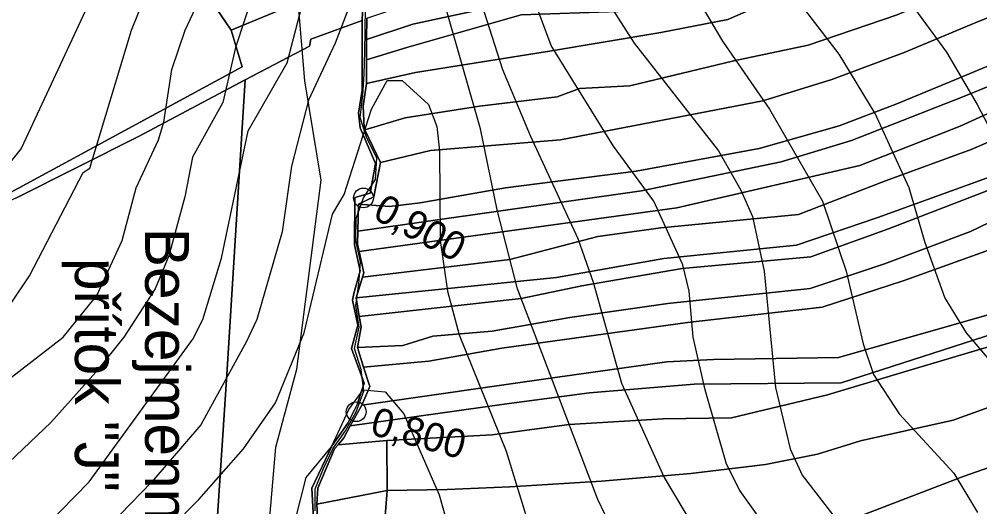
# Model space of a CAD drawing. Extents: x -510989 to -501240, y -1184665 to -1176098.
# Drawn here: x -509222.3 to -508784.4, y -1178657.4 to -1178435 of the extents above; entities that cross this region are included whole.
import ezdxf

# ---------------------------------------------------------------- set-up
doc = ezdxf.new("R2010")
doc.units = 0
for name, color, linetype in [('lesni_pozemek', 7, 'Continuous'), ('NAVRH_rozvodnice', 7, 'Continuous'), ('orna_puda', 7, 'Continuous'), ('ostatni_plocha_x_neplodna_puda', 7, 'Continuous'), ('STAV_systematicke_odvodneni', 7, 'Continuous'), ('trasovani_toku', 7, 'Continuous'), ('trvaly_travni_porost', 7, 'Continuous'), ('vodni_plocha_x_vodni_tok_v_koryt_prir_n_upr', 7, 'Continuous'), ('vrstevnice_01', 7, 'Continuous'), ('vrstevnice_02', 7, 'Continuous')]:
    doc.layers.add(name, color=color, linetype=linetype)

msp = doc.modelspace()

# ---------------------------------------------------------------- linework, layer by layer
at = {"layer": 'lesni_pozemek'}
for points in [[(-508725.81, -1178338.87), (-508747.38, -1178349.86), (-508771.63, -1178361.32), (-508829.64, -1178384.55), (-508872.53, -1178403.38), (-508910.67, -1178417.59), (-508947.16, -1178423.75), (-508989.77, -1178425.71), (-509042.9, -1178437.31), (-509063.9, -1178444.27), (-509063.87, -1178434.51), (-509050.17, -1178430.04), (-508985.42, -1178417.62), (-508954.71, -1178413.25), (-508914.71, -1178412.6), (-508860.28, -1178392.26), (-508835.76, -1178381.15), (-508767.15, -1178352.66), (-508746.52, -1178342.99), (-508726.34, -1178333.53)], [(-508724.96, -1178347.33), (-508750.56, -1178363.13), (-508780.12, -1178374.78), (-508825.23, -1178395.14), (-508865.91, -1178412.19), (-508905.35, -1178425.13), (-508949.3, -1178431.48), (-508993.44, -1178433.03), (-509045.63, -1178447.9), (-509063.93, -1178453.51), (-509063.9, -1178444.27), (-509042.9, -1178437.31), (-508989.77, -1178425.71), (-508947.16, -1178423.75), (-508910.67, -1178417.59), (-508872.53, -1178403.38), (-508829.64, -1178384.55), (-508771.63, -1178361.32), (-508747.38, -1178349.86), (-508725.81, -1178338.87)], [(-508724.96, -1178347.33), (-508723.35, -1178363.5), (-508739.8, -1178372.05), (-508775.1, -1178387.24), (-508823.72, -1178407.29), (-508879.66, -1178426.71), (-508899.31, -1178435.13), (-508929.85, -1178441.05), (-508980.55, -1178449.64), (-509041.66, -1178459.27), (-509063.96, -1178464.29), (-509063.93, -1178453.51), (-509045.63, -1178447.9), (-508993.44, -1178433.03), (-508949.3, -1178431.48), (-508905.35, -1178425.13), (-508865.91, -1178412.19), (-508825.23, -1178395.14), (-508780.12, -1178374.78), (-508750.56, -1178363.13)], [(-508717.91, -1178388.34), (-508711.8, -1178405.03), (-508747.07, -1178420.57), (-508786.54, -1178436.62), (-508818.83, -1178450.27), (-508851.86, -1178462.49), (-508883.28, -1178472.19), (-508975.6, -1178490), (-509034.85, -1178494.89), (-509057.51, -1178500.36), (-509064.65, -1178485.43), (-509046.4, -1178480), (-509012.39, -1178474.7), (-508976.98, -1178470.38), (-508966.94, -1178466.65), (-508943.87, -1178465.37), (-508896.48, -1178453.98), (-508862.6, -1178446.85), (-508822.14, -1178433.03), (-508752.43, -1178402.95)], [(-508710.55, -1178408.46), (-508709.09, -1178426.97), (-508754.59, -1178445.55), (-508797.64, -1178463.43), (-508822.28, -1178473.66), (-508848.44, -1178483.7), (-508884.95, -1178494.03), (-508941.04, -1178504.33), (-509000.63, -1178511.98), (-509039.44, -1178518.8), (-509053.47, -1178520.38), (-509067.62, -1178519.38), (-509060.62, -1178515.98), (-509057.51, -1178500.36), (-509034.85, -1178494.89), (-508975.6, -1178490), (-508883.28, -1178472.19), (-508851.86, -1178462.49), (-508818.83, -1178450.27), (-508786.54, -1178436.62), (-508747.07, -1178420.57), (-508711.8, -1178405.03)], [(-508708.36, -1178436.29), (-508792.21, -1178470.5), (-508842.92, -1178490.3), (-508874.96, -1178500.15), (-508938.58, -1178513.29), (-509067.91, -1178531.72), (-509067.62, -1178519.38), (-509053.47, -1178520.38), (-509039.44, -1178518.8), (-509000.63, -1178511.98), (-508941.04, -1178504.33), (-508884.95, -1178494.03), (-508848.44, -1178483.7), (-508822.28, -1178473.66), (-508797.64, -1178463.43), (-508754.59, -1178445.55), (-508709.09, -1178426.97)], [(-508707.48, -1178447.43), (-508757.4, -1178467.42), (-508793.43, -1178483.76), (-508839.17, -1178501.69), (-508922.58, -1178521.13), (-509067.34, -1178541), (-509068.05, -1178537.65), (-509067.91, -1178531.72), (-508938.58, -1178513.29), (-508874.96, -1178500.15), (-508842.92, -1178490.3), (-508792.21, -1178470.5), (-508708.36, -1178436.29)], [(-508706.46, -1178460.5), (-508722.75, -1178466.14), (-508765.33, -1178484.52), (-508788.4, -1178494.49), (-508827.36, -1178508.75), (-508867.12, -1178524.13), (-508929.73, -1178530.12), (-508958.54, -1178534.17), (-508998.7, -1178544.63), (-509065.84, -1178552.64), (-509065.25, -1178550.72), (-509067.34, -1178541), (-508922.58, -1178521.13), (-508839.17, -1178501.69), (-508793.43, -1178483.76), (-508757.4, -1178467.42), (-508707.48, -1178447.43)], [(-508722.75, -1178466.14), (-508706.46, -1178460.5), (-508705.39, -1178474.04), (-508749.78, -1178494.14), (-508781.31, -1178507.49), (-508830.87, -1178525.39), (-508867.91, -1178538.01), (-508928.36, -1178544.13), (-508977.41, -1178552.83), (-509068.71, -1178562.12), (-509065.84, -1178552.64), (-508998.7, -1178544.63), (-508958.54, -1178534.17), (-508929.73, -1178530.12), (-508867.12, -1178524.13), (-508827.36, -1178508.75), (-508788.4, -1178494.49), (-508765.33, -1178484.52)], [(-508704.77, -1178481.97), (-508738.88, -1178496.86), (-508783.53, -1178514.19), (-508825.98, -1178530.66), (-508861.42, -1178543.38), (-508920.04, -1178548.71), (-508965.85, -1178556.61), (-508993.42, -1178562.43), (-509067.23, -1178570.68), (-509068.71, -1178562.12), (-508977.41, -1178552.83), (-508928.36, -1178544.13), (-508867.91, -1178538.01), (-508830.87, -1178525.39), (-508781.31, -1178507.49), (-508749.78, -1178494.14), (-508705.39, -1178474.04)], [(-508704.31, -1178487.86), (-508702.78, -1178494.41), (-508737.94, -1178507.32), (-508788.64, -1178531.83), (-508827.81, -1178546.52), (-508861.73, -1178557.86), (-508926.56, -1178564.75), (-508971.21, -1178571.08), (-509006.72, -1178577.25), (-509033.74, -1178579.63), (-509047.36, -1178583.77), (-509068.11, -1178584.82), (-509066.42, -1178575.37), (-509067.23, -1178570.68), (-508993.42, -1178562.43), (-508965.85, -1178556.61), (-508920.04, -1178548.71), (-508861.42, -1178543.38), (-508825.98, -1178530.66), (-508783.53, -1178514.19), (-508738.88, -1178496.86), (-508704.77, -1178481.97)], [(-508699.99, -1178506.32), (-508765.23, -1178532.27), (-508781.68, -1178540.86), (-508819.35, -1178554.28), (-508856.26, -1178566.38), (-508917.7, -1178573.41), (-509002.31, -1178585.02), (-509035.54, -1178590.95), (-509065.29, -1178593.71), (-509068.11, -1178584.82), (-509047.36, -1178583.77), (-509033.74, -1178579.63), (-509006.72, -1178577.25), (-508971.21, -1178571.08), (-508926.56, -1178564.75), (-508861.73, -1178557.86), (-508827.81, -1178546.52), (-508788.64, -1178531.83), (-508737.94, -1178507.32), (-508702.78, -1178494.41)], [(-508694.2, -1178531.12), (-508773.17, -1178567.76), (-508848.8, -1178589.27), (-508905.8, -1178590.26), (-508927.09, -1178591.28), (-508977.94, -1178598.38), (-509066.11, -1178611.08), (-509062.51, -1178602.52), (-509065.29, -1178593.71), (-509035.54, -1178590.95), (-509002.31, -1178585.02), (-508917.7, -1178573.41), (-508856.26, -1178566.38), (-508819.35, -1178554.28), (-508781.68, -1178540.86), (-508765.23, -1178532.27), (-508699.99, -1178506.32)], [(-508691.9, -1178539.27), (-508717.79, -1178553.24), (-508749.42, -1178566.28), (-508768.45, -1178575.36), (-508847.66, -1178600.8), (-508914.58, -1178601.44), (-508962.38, -1178605.49), (-509001.19, -1178610.54), (-509071.33, -1178620.51), (-509066.11, -1178611.08), (-508977.94, -1178598.38), (-508927.09, -1178591.28), (-508905.8, -1178590.26), (-508848.8, -1178589.27), (-508773.17, -1178567.76), (-508694.2, -1178531.12)], [(-508689.7, -1178547.08), (-508768.8, -1178580.92), (-508819.34, -1178596.04), (-508853.82, -1178606.35), (-508897.56, -1178616.84), (-508928.77, -1178617.24), (-508971.61, -1178619.89), (-509006.67, -1178624.56), (-509054.7, -1178627.16), (-509076.91, -1178629.11), (-509074.36, -1178626), (-509071.33, -1178620.51), (-509001.19, -1178610.54), (-508962.38, -1178605.49), (-508914.58, -1178601.44), (-508847.66, -1178600.8), (-508768.45, -1178575.36), (-508749.42, -1178566.28), (-508717.79, -1178553.24), (-508691.9, -1178539.27)], [(-508685.06, -1178563.52), (-508683.92, -1178574.65), (-508712.94, -1178585.61), (-508741.33, -1178597.92), (-508796.54, -1178617.89), (-508838.72, -1178627.31), (-508858.45, -1178633.41), (-508882.13, -1178638.15), (-508916.08, -1178642.26), (-508956.82, -1178645.68), (-508998.59, -1178648.35), (-509027.25, -1178649.57), (-509054.58, -1178650.03), (-509054.7, -1178627.16), (-509006.67, -1178624.56), (-508971.61, -1178619.89), (-508928.77, -1178617.24), (-508897.56, -1178616.84), (-508853.82, -1178606.35), (-508819.34, -1178596.04), (-508768.8, -1178580.92), (-508689.7, -1178547.08)], [(-508712.94, -1178585.61), (-508683.92, -1178574.65), (-508680.85, -1178604.64), (-508791.99, -1178643.51), (-508888.15, -1178680.51), (-508882.24, -1178674), (-508884.37, -1178665.06), (-508955.25, -1178684.75), (-508960.15, -1178669.29), (-509059.22, -1178683.03), (-509056.08, -1178669.28), (-509054.58, -1178650.03), (-509027.25, -1178649.57), (-508998.59, -1178648.35), (-508956.82, -1178645.68), (-508916.08, -1178642.26), (-508882.13, -1178638.15), (-508858.45, -1178633.41), (-508838.72, -1178627.31), (-508796.54, -1178617.89), (-508741.33, -1178597.92)], [(-508680.85, -1178604.64), (-508669.27, -1178651.7), (-508749.47, -1178676.41), (-508794.13, -1178696.5), (-508842.69, -1178719.84), (-508894.51, -1178744.76), (-508906.64, -1178707.76), (-508907.44, -1178701.76), (-508888.15, -1178680.51), (-508791.99, -1178643.51)]]:
    msp.add_lwpolyline(points, close=True, dxfattribs=at)
msp.add_lwpolyline([(-508752.43, -1178402.95), (-508822.14, -1178433.03), (-508862.6, -1178446.85), (-508896.48, -1178453.98), (-508943.87, -1178465.37), (-508966.94, -1178466.65), (-508976.98, -1178470.38), (-509012.39, -1178474.7), (-509046.4, -1178480), (-509064.65, -1178485.43), (-509065.08, -1178484.53), (-509065.42, -1178474.76), (-509063.96, -1178464.29), (-509041.66, -1178459.27), (-508980.55, -1178449.64), (-508929.85, -1178441.05), (-508899.31, -1178435.13), (-508879.66, -1178426.71), (-508823.72, -1178407.29), (-508775.1, -1178387.24)], dxfattribs=at)
at = {"layer": 'orna_puda'}
msp.add_lwpolyline([(-509136.21, -1178728.22), (-509127.44, -1178594.74), (-509119.19, -1178462.76), (-509089.96, -1178447.33), (-509089.35, -1178444.08), (-509065.99, -1178435.56), (-509065.97, -1178467.35), (-509067.53, -1178477.84), (-509066.87, -1178484.6), (-509059.92, -1178500.82), (-509062.23, -1178514.38), (-509069.22, -1178516.36), (-509069.47, -1178537.93), (-509066.85, -1178549.86), (-509069.78, -1178560.1), (-509070.28, -1178563.21), (-509067.97, -1178574.57), (-509070.81, -1178585.19), (-509064.96, -1178601), (-509068.2, -1178610.67), (-509072.47, -1178619.27), (-509079.57, -1178629.42), (-509088.82, -1178648.83), (-509087.14, -1178679.95)], dxfattribs=at)
at = {"layer": 'ostatni_plocha_x_neplodna_puda'}
msp.add_lwpolyline([(-509072.63, -1178417.97), (-509065.13, -1178416.66), (-509065.99, -1178435.56), (-509089.35, -1178444.08), (-509089.96, -1178447.33), (-509119.19, -1178462.76), (-509167.87, -1178488.46), (-509223.82, -1178516.62), (-509235.9, -1178521.93), (-509237.05, -1178519.8), (-509120.69, -1178456.83), (-509125.72, -1178439.98)], close=True, dxfattribs=at)
at = {"layer": 'STAV_systematicke_odvodneni'}
for p, q in [((-509092.01, -1178463.16), (-509095.74, -1178418.45)), ((-509084.57, -1178508.4), (-509092.01, -1178463.16)), ((-509095.74, -1178594.61), (-509084.57, -1178508.4)), ((-509105.31, -1178630.27), (-509095.74, -1178594.61)), ((-509110.1, -1178685.09), (-509105.31, -1178630.27))]:
    msp.add_line(p, q, dxfattribs=at)
at = {"layer": 'trasovani_toku'}
for p, q in [((-509064.6, -1178439.91), (-509064.38, -1178429.92)), ((-509064.77, -1178449.91), (-509064.6, -1178439.91)), ((-509065.01, -1178459.91), (-509064.77, -1178449.91)), ((-509065.69, -1178469.89), (-509065.01, -1178459.91)), ((-509066.88, -1178479.82), (-509065.69, -1178469.89)), ((-509063.87, -1178489.35), (-509066.88, -1178479.82)), ((-509059.25, -1178498.22), (-509063.87, -1178489.35)), ((-509059.8, -1178508.2), (-509059.25, -1178498.22)), ((-509065.34, -1178516.53), (-509059.8, -1178508.2)), ((-509068.67, -1178525.96), (-509065.34, -1178516.53)), ((-509068.81, -1178535.96), (-509068.67, -1178525.96)), ((-509066.73, -1178545.74), (-509068.81, -1178535.96)), ((-509067.46, -1178555.71), (-509066.73, -1178545.74)), ((-509068.83, -1178565.62), (-509067.46, -1178555.71)), ((-509067.23, -1178575.49), (-509068.83, -1178565.62)), ((-509069.46, -1178585.24), (-509067.23, -1178575.49)), ((-509066.33, -1178594.73), (-509069.46, -1178585.24)), ((-509065.14, -1178604.66), (-509066.33, -1178594.73)), ((-509068.66, -1178614.02), (-509065.14, -1178604.66)), ((-509073.5, -1178622.77), (-509068.66, -1178614.02)), ((-509079.23, -1178630.97), (-509073.5, -1178622.77)), ((-509083.54, -1178639.99), (-509079.23, -1178630.97)), ((-509087.38, -1178649.22), (-509083.54, -1178639.99)), ((-509087.3, -1178659.22), (-509087.38, -1178649.22))]:
    msp.add_line(p, q, dxfattribs=at)
for centre in [(-509065.34, -1178516.53), (-509068.66, -1178614.02)]:
    msp.add_circle(centre, 4.5, dxfattribs=at)
at = {"layer": 'trvaly_travni_porost'}
for points in [[(-509277.34, -1178339.91), (-509215.44, -1178310.62), (-509195.58, -1178302.7), (-509186.3, -1178325.96), (-509193.66, -1178336.5), (-509167.9, -1178335.7), (-509155.84, -1178350.78), (-509153.73, -1178362.47), (-509152.2, -1178398.94), (-509160.65, -1178402.19), (-509152.6, -1178400.3), (-509125.72, -1178439.98), (-509120.69, -1178456.83), (-509237.05, -1178519.8)], [(-509223.82, -1178516.62), (-509167.87, -1178488.46), (-509119.19, -1178462.76), (-509127.44, -1178594.74), (-509136.21, -1178728.22)]]:
    msp.add_lwpolyline(points, dxfattribs=at)
for points in [[(-509074.62, -1178378.22), (-509061.57, -1178375.25), (-509065.13, -1178416.66), (-509072.63, -1178417.97), (-509125.72, -1178439.98), (-509152.6, -1178400.3), (-509136.97, -1178396.64), (-509107.42, -1178384.13), (-509104.85, -1178388.43)], [(-509054.7, -1178627.16), (-509054.58, -1178650.03), (-509086.62, -1178656.21), (-509086.14, -1178648.85), (-509078.48, -1178631.01), (-509076.91, -1178629.11)], [(-509086.62, -1178656.21), (-509054.58, -1178650.03), (-509056.08, -1178669.28), (-509059.22, -1178683.03), (-509058.69, -1178692.51), (-508958.61, -1178704.53), (-508882.24, -1178674), (-508888.15, -1178680.51), (-508907.44, -1178701.76), (-508906.64, -1178707.76), (-508915.45, -1178716.88), (-508925.43, -1178723.64), (-508930.53, -1178717.43), (-508937.49, -1178718.86), (-508941.58, -1178715.83), (-508975.78, -1178721.18), (-508991.88, -1178719.79), (-509002.41, -1178711.97), (-509041.89, -1178717.09), (-509093.21, -1178732.21), (-509082.25, -1178699.18), (-509085.42, -1178679.89)]]:
    msp.add_lwpolyline(points, close=True, dxfattribs=at)
at = {"layer": 'vodni_plocha_x_vodni_tok_v_koryt_prir_n_upr'}
for points in [[(-509087.14, -1178679.95), (-509088.82, -1178648.83), (-509079.57, -1178629.42), (-509072.47, -1178619.27), (-509068.2, -1178610.67), (-509064.96, -1178601), (-509070.81, -1178585.19), (-509067.97, -1178574.57), (-509070.28, -1178563.21), (-509069.78, -1178560.1), (-509066.85, -1178549.86), (-509069.47, -1178537.93), (-509069.22, -1178516.36), (-509062.23, -1178514.38), (-509059.92, -1178500.82), (-509066.87, -1178484.6), (-509067.53, -1178477.84), (-509065.97, -1178467.35), (-509065.99, -1178435.56), (-509065.13, -1178416.66)], [(-509063.87, -1178434.51), (-509063.9, -1178444.27), (-509063.93, -1178453.51), (-509063.96, -1178464.29), (-509065.42, -1178474.76), (-509065.08, -1178484.53), (-509064.65, -1178485.43), (-509057.51, -1178500.36), (-509060.62, -1178515.98), (-509067.62, -1178519.38), (-509067.91, -1178531.72), (-509068.05, -1178537.65), (-509067.34, -1178541), (-509065.25, -1178550.72), (-509065.84, -1178552.64), (-509068.71, -1178562.12), (-509067.23, -1178570.68), (-509066.42, -1178575.37), (-509068.11, -1178584.82), (-509065.29, -1178593.71), (-509062.51, -1178602.52), (-509066.11, -1178611.08), (-509071.33, -1178620.51), (-509074.36, -1178626), (-509076.91, -1178629.11), (-509078.48, -1178631.01), (-509086.14, -1178648.85), (-509086.62, -1178656.21), (-509085.42, -1178679.89)]]:
    msp.add_lwpolyline(points, dxfattribs=at)
at = {"layer": 'vrstevnice_01'}
for points in [[(-509078.41, -1178186), (-509093.09, -1178204), (-509103.41, -1178224), (-509120.69, -1178272), (-509126.91, -1178285), (-509128, -1178286), (-509132.41, -1178303), (-509157, -1178359), (-509179.31, -1178402), (-509182.59, -1178411), (-509186.31, -1178416), (-509192, -1178431), (-509221.41, -1178494), (-509235.19, -1178511)], [(-508736.09, -1178670), (-508738.31, -1178653), (-508742.81, -1178640), (-508754.81, -1178620), (-508790.41, -1178578), (-508800.31, -1178562), (-508809.31, -1178537), (-508816.59, -1178512), (-508832.09, -1178478), (-508848.59, -1178451), (-508875.19, -1178416), (-508893.41, -1178390), (-508905, -1178371), (-508937.41, -1178310), (-508971.91, -1178238), (-508988.41, -1178211), (-508999.69, -1178197)], [(-509210, -1178666), (-509190.31, -1178646), (-509143.19, -1178581), (-509138.59, -1178572), (-509130.09, -1178544), (-509117.91, -1178486), (-509100.09, -1178455), (-509092.41, -1178425), (-509066.19, -1178344), (-509053.31, -1178328), (-509040.91, -1178326), (-509035.31, -1178329), (-509031.81, -1178333), (-509028.91, -1178340), (-509025.09, -1178356), (-509020.81, -1178390), (-509015.41, -1178416), (-509001.91, -1178458), (-508989.41, -1178488), (-508967.59, -1178535), (-508960.59, -1178555), (-508947.69, -1178601), (-508928.31, -1178644), (-508905.69, -1178682)], [(-509232, -1178603), (-509202.19, -1178580), (-509186.81, -1178561), (-509175.31, -1178536), (-509169, -1178512), (-509158.81, -1178490), (-509156.41, -1178482), (-509152.69, -1178458), (-509146.59, -1178440), (-509135.81, -1178417)], [(-508956.5, -1178423), (-508942, -1178446), (-508903.5, -1178495), (-508893.31, -1178513), (-508888.09, -1178525), (-508882.69, -1178550), (-508877.5, -1178603), (-508870.91, -1178631), (-508865.31, -1178643), (-508851.41, -1178661)], [(-509152.77, -1178666.68), (-509140.31, -1178654), (-509120, -1178631), (-509105.5, -1178610), (-509092.31, -1178578), (-509079.41, -1178524), (-509074.19, -1178515), (-509061.69, -1178476), (-509054.59, -1178463), (-509047.69, -1178463), (-509035.69, -1178474), (-509031.91, -1178484), (-509030.69, -1178495), (-509030.41, -1178536), (-509027.09, -1178559), (-509021.69, -1178579), (-509000.31, -1178632), (-508984.91, -1178682)]]:
    msp.add_lwpolyline(points, dxfattribs=at)
at = {"layer": 'vrstevnice_02'}
for points in [[(-508981.81, -1178183), (-508956.5, -1178215), (-508940.91, -1178239), (-508902.81, -1178301), (-508874.09, -1178352), (-508853.5, -1178384), (-508817, -1178426), (-508799.59, -1178450), (-508785.59, -1178474), (-508761.41, -1178520), (-508748.5, -1178541), (-508729.91, -1178563), (-508705, -1178587), (-508684.69, -1178614), (-508680.19, -1178625), (-508677.31, -1178639), (-508676.09, -1178671)], [(-509025.31, -1178199), (-509006.31, -1178217), (-508999, -1178229), (-508996.31, -1178230), (-508995.41, -1178235), (-508978.69, -1178282), (-508955.19, -1178342), (-508929.5, -1178398), (-508901.69, -1178445), (-508880.31, -1178476), (-508856.09, -1178518), (-508845.31, -1178550), (-508837.59, -1178583), (-508832.81, -1178597), (-508821.19, -1178615), (-508796.19, -1178642), (-508785.41, -1178660)], [(-509225.69, -1178564), (-509217.5, -1178552), (-509193.09, -1178505), (-509190.09, -1178503), (-509171.09, -1178440), (-509152.59, -1178394), (-509130.91, -1178352), (-509107.69, -1178287), (-509093.19, -1178265), (-509088.81, -1178254), (-509082.41, -1178229), (-509071.81, -1178212), (-509060.19, -1178201)], [(-508938.5, -1178696), (-508958.5, -1178654), (-508995.19, -1178558), (-509004.41, -1178522), (-509012, -1178485), (-509027.19, -1178432), (-509035.31, -1178396), (-509044.41, -1178384), (-509050, -1178382), (-509054.81, -1178385), (-509078.31, -1178446), (-509090.41, -1178472), (-509098.19, -1178502), (-509102.41, -1178532), (-509114, -1178572), (-509118.59, -1178582), (-509139.5, -1178620), (-509161.81, -1178646), (-509233.69, -1178720)], [(-509107.19, -1178398), (-509123.69, -1178448), (-509129.5, -1178473), (-509143.31, -1178498), (-509146.81, -1178516), (-509154, -1178543), (-509160.31, -1178558), (-509174.59, -1178580), (-509187.31, -1178596), (-509207.81, -1178619), (-509226.91, -1178637)], [(-508868.69, -1178685), (-508893.81, -1178650), (-508899.81, -1178638), (-508909.59, -1178604), (-508915.09, -1178580), (-508916.81, -1178559), (-508919.81, -1178547), (-508933, -1178518), (-508951.31, -1178493), (-508979.81, -1178447), (-508995.81, -1178404)], [(-509096.09, -1178662), (-509091.5, -1178644), (-509079.91, -1178630), (-509072, -1178613), (-509065.5, -1178604), (-509055.5, -1178605), (-509046.91, -1178615), (-509030.91, -1178652), (-509020.91, -1178687)]]:
    msp.add_lwpolyline(points, dxfattribs=at)

# ---------------------------------------------------------------- texts
at = {"layer": 'NAVRH_rozvodnice'}
for s, p in [('Bezejmenný', (-509164.86, -1178530.18)), ('přítok "J"', (-509196.86, -1178543.9))]:
    msp.add_text(s, height=20, rotation=270, dxfattribs=at).set_placement(p)
at = {"layer": 'trasovani_toku'}
for s, rotation, p in [('0,900', 332.0278, (-509061.68, -1178525.6)), ('0,800', 344.6322, (-509062.82, -1178624.23))]:
    msp.add_text(s, height=13, rotation=rotation, dxfattribs=at).set_placement(p)

doc.saveas('drawing.dxf')
